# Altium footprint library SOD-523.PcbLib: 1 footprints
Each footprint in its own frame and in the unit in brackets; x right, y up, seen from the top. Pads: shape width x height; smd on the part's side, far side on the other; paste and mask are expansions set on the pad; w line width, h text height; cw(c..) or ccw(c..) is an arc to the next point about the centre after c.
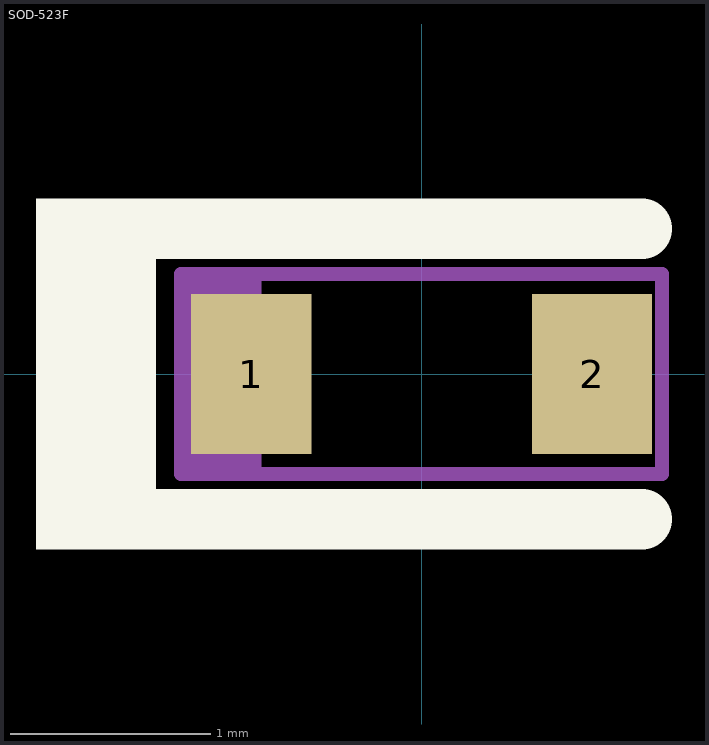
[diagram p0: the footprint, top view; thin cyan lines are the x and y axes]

## SOD-523F [mm] "COMCHIP"
height 0.85
pads (2):
  rect 0.6x0.8 smd paste-0.05: 1(-0.85,0) 2(0.85,0)
Top Overlay:
  rectangle: -1.925,-0.875 -1.325,0.875
  lines w0.3: -1.5,-0.725 1.1,-0.725 ; -1.5,0.725 1.1,0.725
M5 Assembly Top:
  rectangle: -1.2,-0.5 -0.8,0.5
  lines w0.07: -1.2,-0.5 1.2,-0.5 1.2,0.5 -1.2,0.5 -1.2,-0.5
  text ".Designator" at -0.675,-0.275 h0.46
3D body: height 0.85, standoff 0, extent -0.899,-0.499 0.899,0.499
3D body: height 0.85, standoff 0.84, extent -0.899,-0.499 -0.401,0.499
